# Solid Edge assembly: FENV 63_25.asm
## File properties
Title: Zylinder
Author: bmolnar
Template: iso assembly.asm
Last saved by: bmolnar
Revision: 12
Application: Solid Edge
Username: bmolnar
Dokumentum tartalom típus: 1
Document Number: FENV 63/25
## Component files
Kit_1.par
Profilrohr.par
Kit_2.par
Kolbenstange.par
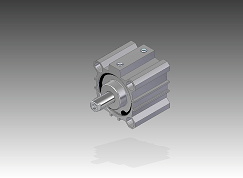
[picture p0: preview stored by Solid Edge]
